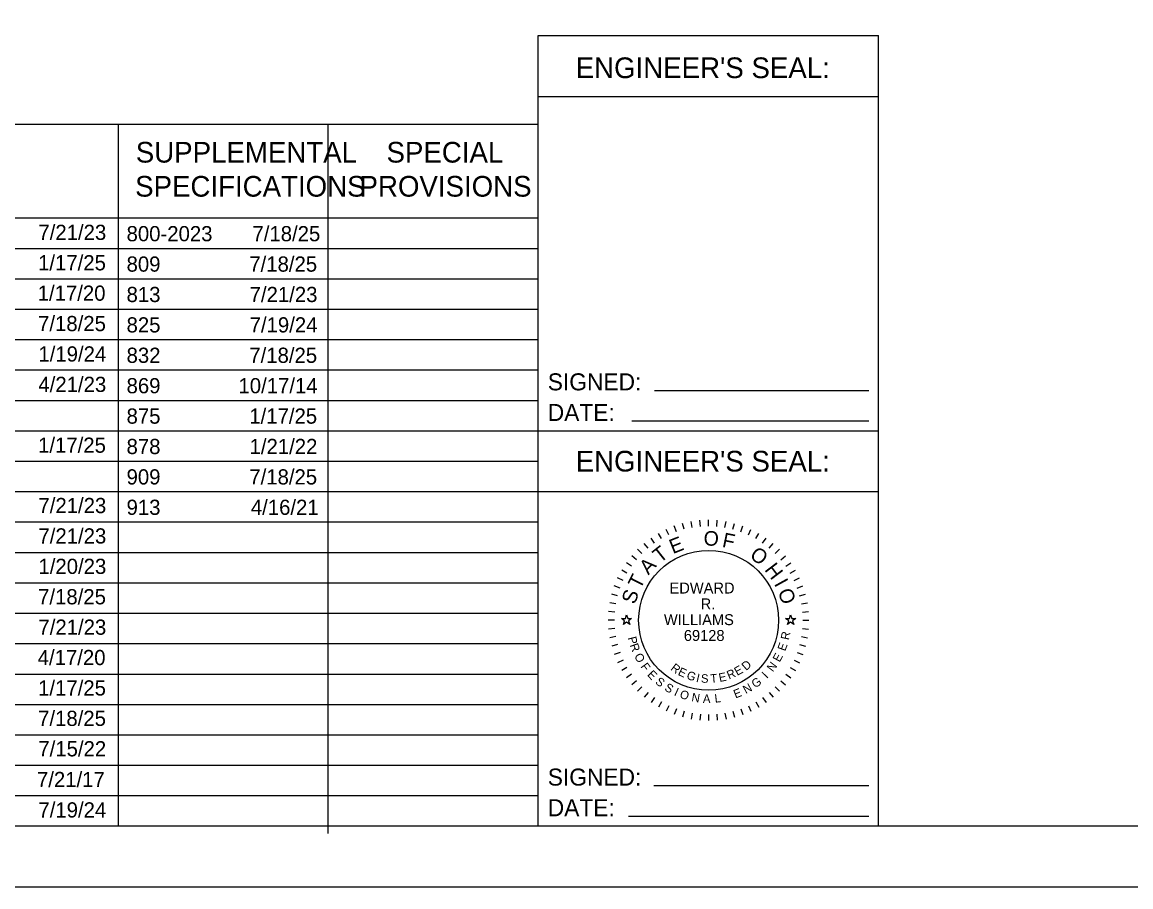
# Model space of a CAD drawing. Extents: x -7.5 to 26.5, y 3.5 to 25.5.
# Drawn here: x 12.51 to 21.63, y 3.5 to 10.61 of the extents above; entities that cross this region are included whole.
import ezdxf

# ---------------------------------------------------------------- set-up
doc = ezdxf.new("R2010")
doc.units = 0
for name, color, linetype in [('SH_Border', 7, 'Continuous'), ('SH_Cut_Line', 7, 'Continuous'), ('SH_Data', 7, 'Continuous'), ('SH_Text', 7, 'Continuous')]:
    doc.layers.add(name, color=color, linetype=linetype)

msp = doc.modelspace()

# ---------------------------------------------------------------- linework, layer by layer
at = {"layer": 'SH_Border'}
msp.add_lwpolyline([(-5.9569, 25), (26.0431, 25), (26.0431, 4), (-5.9569, 4)], close=True, dxfattribs=at)
at = {"layer": 'SH_Cut_Line'}
msp.add_lwpolyline([(-7.4569, 3.5), (26.5431, 3.5), (26.5431, 25.5), (-7.4569, 25.5)], close=True, dxfattribs=at)
at = {"layer": 'SH_Data'}
for p, q in [((16.7556, 7.25), (16.7556, 10.5)), ((16.7556, 10.5), (19.5556, 10.5)), ((19.5556, 4), (19.5556, 10.5)), ((16.7556, 10), (19.5556, 10)), ((1.3056, 9.7708), (16.7556, 9.7708)), ((13.3056, 4), (13.3056, 9.7708)), ((15.0306, 3.9373), (15.0306, 9.7708)), ((1.3056, 9), (16.7556, 9)), ((16.7556, 4), (16.7556, 8.7918)), ((1.3056, 8.75), (16.7556, 8.75)), ((1.3056, 8.5), (16.7556, 8.5)), ((1.3056, 8.25), (16.7556, 8.25)), ((1.3056, 8), (16.7556, 8)), ((1.3056, 7.75), (16.7556, 7.75)), ((1.3056, 7.5), (16.7556, 7.5)), ((1.3056, 7.25), (16.7556, 7.25)), ((16.7556, 4), (16.7556, 7.25)), ((16.7556, 7.25), (19.5556, 7.25)), ((1.3056, 7), (16.7556, 7)), ((1.3056, 6.75), (16.7556, 6.75)), ((16.7556, 6.75), (19.5556, 6.75)), ((1.3056, 6.5), (16.7556, 6.5)), ((1.3056, 6.25), (16.7556, 6.25)), ((1.3056, 6), (16.7556, 6)), ((1.3056, 5.75), (16.7556, 5.75)), ((1.3056, 5.5), (16.7556, 5.5)), ((1.3056, 5.25), (16.7556, 5.25)), ((1.3056, 5), (16.7556, 5)), ((1.3056, 4.75), (16.7556, 4.75)), ((1.3056, 4.5), (16.7556, 4.5)), ((1.3056, 4.25), (16.7556, 4.25))]:
    msp.add_line(p, q, dxfattribs=at)
at = {"layer": 'SH_Text'}
for p, q in [((17.7138, 7.5824), (19.4769, 7.5824)), ((17.5276, 7.3305), (19.4769, 7.3305)), ((17.9576, 6.4405), (17.9447, 6.4888)), ((17.9576, 6.4405), (17.9447, 6.4888)), ((18.0236, 6.4551), (18.015, 6.5043)), ((18.0236, 6.4551), (18.015, 6.5043)), ((18.0907, 6.4639), (18.0863, 6.5137)), ((18.0907, 6.4639), (18.0863, 6.5137)), ((18.1582, 6.4669), (18.1582, 6.5169)), ((18.1582, 6.4669), (18.1582, 6.5169)), ((18.2258, 6.4639), (18.2301, 6.5137)), ((18.2258, 6.4639), (18.2301, 6.5137)), ((18.2928, 6.4551), (18.3015, 6.5043)), ((18.2928, 6.4551), (18.3015, 6.5043)), ((18.3588, 6.4405), (18.3717, 6.4888)), ((18.3588, 6.4405), (18.3717, 6.4888)), ((17.7707, 6.3631), (17.7457, 6.4064)), ((17.7707, 6.3631), (17.7457, 6.4064)), ((17.8307, 6.3943), (17.8096, 6.4396)), ((17.8307, 6.3943), (17.8096, 6.4396)), ((17.8932, 6.4201), (17.8761, 6.4671)), ((17.8932, 6.4201), (17.8761, 6.4671)), ((18.4233, 6.4201), (18.4404, 6.4671)), ((18.4233, 6.4201), (18.4404, 6.4671)), ((18.4857, 6.3943), (18.5069, 6.4396)), ((18.4857, 6.3943), (18.5069, 6.4396)), ((18.5457, 6.3631), (18.5707, 6.4064)), ((18.5457, 6.3631), (18.5707, 6.4064)), ((17.6601, 6.2856), (17.6279, 6.3239)), ((17.6601, 6.2856), (17.6279, 6.3239)), ((17.7137, 6.3267), (17.685, 6.3677)), ((17.7137, 6.3267), (17.685, 6.3677)), ((18.6027, 6.3267), (18.6314, 6.3677)), ((18.6027, 6.3267), (18.6314, 6.3677)), ((18.6564, 6.2856), (18.6885, 6.3239)), ((18.6564, 6.2856), (18.6885, 6.3239)), ((17.5645, 6.19), (17.5262, 6.2222)), ((17.5645, 6.19), (17.5262, 6.2222)), ((17.6102, 6.2399), (17.5749, 6.2752)), ((17.6102, 6.2399), (17.5749, 6.2752)), ((18.7062, 6.2399), (18.7416, 6.2752)), ((18.7062, 6.2399), (18.7416, 6.2752)), ((18.7519, 6.19), (18.7902, 6.2222)), ((18.7519, 6.19), (18.7902, 6.2222)), ((17.5234, 6.1364), (17.4824, 6.1651)), ((17.5234, 6.1364), (17.4824, 6.1651)), ((18.7931, 6.1364), (18.834, 6.1651)), ((18.7931, 6.1364), (18.834, 6.1651)), ((17.4558, 6.0194), (17.4105, 6.0405)), ((17.4558, 6.0194), (17.4105, 6.0405)), ((17.4871, 6.0794), (17.4438, 6.1044)), ((17.4871, 6.0794), (17.4438, 6.1044)), ((18.8294, 6.0794), (18.8727, 6.1044)), ((18.8294, 6.0794), (18.8727, 6.1044)), ((18.8606, 6.0194), (18.9059, 6.0405)), ((18.8606, 6.0194), (18.9059, 6.0405)), ((17.43, 5.9569), (17.383, 5.974)), ((17.43, 5.9569), (17.383, 5.974)), ((18.8865, 5.9569), (18.9335, 5.974)), ((18.8865, 5.9569), (18.9335, 5.974)), ((17.395, 5.8265), (17.3458, 5.8351)), ((17.395, 5.8265), (17.3458, 5.8351)), ((17.4096, 5.8925), (17.3613, 5.9054)), ((17.4096, 5.8925), (17.3613, 5.9054)), ((18.9068, 5.8925), (18.9551, 5.9054)), ((18.9068, 5.8925), (18.9551, 5.9054)), ((18.9214, 5.8265), (18.9707, 5.8351)), ((18.9214, 5.8265), (18.9707, 5.8351)), ((17.3862, 5.7594), (17.3364, 5.7638)), ((17.3862, 5.7594), (17.3364, 5.7638)), ((18.9303, 5.7594), (18.9801, 5.7638)), ((18.9303, 5.7594), (18.9801, 5.7638)), ((17.3832, 5.6919), (17.3332, 5.6919)), ((17.3832, 5.6919), (17.3332, 5.6919)), ((18.9332, 5.6919), (18.9832, 5.6919)), ((18.9332, 5.6919), (18.9832, 5.6919)), ((17.3862, 5.6243), (17.3364, 5.62)), ((17.3862, 5.6243), (17.3364, 5.62)), ((18.9303, 5.6243), (18.9801, 5.62)), ((18.9303, 5.6243), (18.9801, 5.62)), ((17.395, 5.5573), (17.3458, 5.5486)), ((17.395, 5.5573), (17.3458, 5.5486)), ((17.4096, 5.4913), (17.3613, 5.4784)), ((17.4096, 5.4913), (17.3613, 5.4784)), ((18.9068, 5.4913), (18.9551, 5.4784)), ((18.9068, 5.4913), (18.9551, 5.4784)), ((18.9214, 5.5573), (18.9707, 5.5486)), ((18.9214, 5.5573), (18.9707, 5.5486)), ((17.43, 5.4268), (17.383, 5.4097)), ((17.43, 5.4268), (17.383, 5.4097)), ((18.8865, 5.4268), (18.9335, 5.4097)), ((18.8865, 5.4268), (18.9335, 5.4097)), ((17.4558, 5.3644), (17.4105, 5.3432)), ((17.4558, 5.3644), (17.4105, 5.3432)), ((17.4871, 5.3044), (17.4438, 5.2794)), ((17.4871, 5.3044), (17.4438, 5.2794)), ((18.8294, 5.3044), (18.8727, 5.2794)), ((18.8294, 5.3044), (18.8727, 5.2794)), ((18.8606, 5.3644), (18.9059, 5.3432)), ((18.8606, 5.3644), (18.9059, 5.3432)), ((17.5234, 5.2474), (17.4824, 5.2187)), ((17.5234, 5.2474), (17.4824, 5.2187)), ((18.7931, 5.2474), (18.834, 5.2187)), ((18.7931, 5.2474), (18.834, 5.2187)), ((17.5645, 5.1937), (17.5262, 5.1616)), ((17.5645, 5.1937), (17.5262, 5.1616)), ((17.6102, 5.1439), (17.5749, 5.1085)), ((17.6102, 5.1439), (17.5749, 5.1085)), ((18.7062, 5.1439), (18.7416, 5.1085)), ((18.7062, 5.1439), (18.7416, 5.1085)), ((18.7519, 5.1937), (18.7902, 5.1616)), ((18.7519, 5.1937), (18.7902, 5.1616)), ((17.6601, 5.0982), (17.6279, 5.0599)), ((17.6601, 5.0982), (17.6279, 5.0599)), ((17.7137, 5.057), (17.685, 5.0161)), ((17.7137, 5.057), (17.685, 5.0161)), ((17.7707, 5.0207), (17.7457, 4.9774)), ((17.7707, 5.0207), (17.7457, 4.9774)), ((18.5457, 5.0207), (18.5707, 4.9774)), ((18.5457, 5.0207), (18.5707, 4.9774)), ((18.6027, 5.057), (18.6314, 5.0161)), ((18.6027, 5.057), (18.6314, 5.0161)), ((18.6564, 5.0982), (18.6885, 5.0599)), ((18.6564, 5.0982), (18.6885, 5.0599)), ((17.8307, 4.9895), (17.8096, 4.9442)), ((17.8307, 4.9895), (17.8096, 4.9442)), ((17.8932, 4.9636), (17.8761, 4.9166)), ((17.8932, 4.9636), (17.8761, 4.9166)), ((17.9576, 4.9433), (17.9447, 4.895)), ((17.9576, 4.9433), (17.9447, 4.895)), ((18.0236, 4.9287), (18.015, 4.8794)), ((18.0236, 4.9287), (18.015, 4.8794)), ((18.2928, 4.9287), (18.3015, 4.8794)), ((18.2928, 4.9287), (18.3015, 4.8794)), ((18.3588, 4.9433), (18.3717, 4.895)), ((18.3588, 4.9433), (18.3717, 4.895)), ((18.4233, 4.9636), (18.4404, 4.9166)), ((18.4233, 4.9636), (18.4404, 4.9166)), ((18.4857, 4.9895), (18.5069, 4.9442)), ((18.4857, 4.9895), (18.5069, 4.9442)), ((18.0907, 4.9198), (18.0863, 4.87)), ((18.0907, 4.9198), (18.0863, 4.87)), ((18.1582, 4.9169), (18.1582, 4.8669)), ((18.1582, 4.9169), (18.1582, 4.8669)), ((18.2258, 4.9198), (18.2301, 4.87)), ((18.2258, 4.9198), (18.2301, 4.87)), ((17.7067, 4.3324), (19.4769, 4.3324)), ((17.499, 4.0805), (19.4769, 4.0805))]:
    msp.add_line(p, q, dxfattribs=at)
for points in [[(17.4837, 5.7356), (17.4935, 5.7054), (17.5253, 5.7054), (17.4996, 5.6867), (17.5094, 5.6565), (17.4837, 5.6752), (17.458, 5.6565), (17.4679, 5.6867), (17.4422, 5.7054), (17.4739, 5.7054)], [(17.4837, 5.7356), (17.4935, 5.7054), (17.5253, 5.7054), (17.4996, 5.6867), (17.5094, 5.6565), (17.4837, 5.6752), (17.458, 5.6565), (17.4679, 5.6867), (17.4422, 5.7054), (17.4739, 5.7054)], [(18.8327, 5.7356), (18.8425, 5.7054), (18.8743, 5.7054), (18.8486, 5.6867), (18.8584, 5.6565), (18.8327, 5.6752), (18.807, 5.6565), (18.8168, 5.6867), (18.7912, 5.7054), (18.8229, 5.7054)], [(18.8327, 5.7356), (18.8425, 5.7054), (18.8743, 5.7054), (18.8486, 5.6867), (18.8584, 5.6565), (18.8327, 5.6752), (18.807, 5.6565), (18.8168, 5.6867), (18.7912, 5.7054), (18.8229, 5.7054)]]:
    msp.add_lwpolyline(points, close=True, dxfattribs=at)
msp.add_circle((18.1582, 5.6919), 0.575, dxfattribs=at)
msp.add_circle((18.1582, 5.6919), 0.575, dxfattribs=at)

# ---------------------------------------------------------------- texts
for s, height, p in [("ENGINEER'S SEAL:", 0.17, (17.0651, 10.15)), ('SUPPLEMENTAL', 0.17, (13.4481, 9.4554)), ('SPECIAL', 0.17, (15.5098, 9.4554)), ('SPECIFICATIONS', 0.17, (13.4426, 9.1754)), ('PROVISIONS', 0.17, (15.2879, 9.1754)), ('7/21/23', 0.125, (12.6473, 8.8193)), ('800-2023', 0.125, (13.3722, 8.8084)), ('7/18/25', 0.125, (14.4074, 8.8084)), ('1/17/25', 0.125, (12.6446, 8.5693)), ('809', 0.125, (13.3722, 8.5584)), ('7/18/25', 0.125, (14.3815, 8.5584)), ('1/17/20', 0.125, (12.6412, 8.3193)), ('813', 0.125, (13.3722, 8.3084)), ('7/21/23', 0.125, (14.3842, 8.3084)), ('7/18/25', 0.125, (12.6446, 8.0693)), ('825', 0.125, (13.3722, 8.0584)), ('7/19/24', 0.125, (14.3842, 8.0584)), ('1/19/24', 0.125, (12.6473, 7.8193)), ('832', 0.125, (13.3722, 7.8084)), ('7/18/25', 0.125, (14.3815, 7.8084)), ('4/21/23', 0.125, (12.6473, 7.5693)), ('869', 0.125, (13.3722, 7.5584)), ('10/17/14', 0.125, (14.2924, 7.5584)), ('SIGNED:', 0.14, (16.8356, 7.5824)), ('875', 0.125, (13.3722, 7.3084)), ('1/17/25', 0.125, (14.3815, 7.3084)), ('DATE:', 0.14, (16.8356, 7.3305)), ('1/17/25', 0.125, (12.6446, 7.0693)), ('878', 0.125, (13.3722, 7.0584)), ('1/21/22', 0.125, (14.3836, 7.0584)), ("ENGINEER'S SEAL:", 0.17, (17.0651, 6.915)), ('909', 0.125, (13.3722, 6.8084)), ('7/18/25', 0.125, (14.3815, 6.8084)), ('7/21/23', 0.125, (12.6476, 6.5729)), ('913', 0.125, (13.3722, 6.5584)), ('4/16/21', 0.125, (14.3942, 6.5584)), ('7/21/23', 0.125, (12.6476, 6.3229)), ('1/20/23', 0.125, (12.6476, 6.0729)), ('7/18/25', 0.125, (12.6449, 5.8229)), ('EDWARD', 0.09, (17.8369, 5.9119)), ('R.', 0.09, (18.0928, 5.7819)), ('7/21/23', 0.125, (12.6476, 5.5729)), ('WILLIAMS', 0.09, (17.7909, 5.6519)), ('69128', 0.09, (17.9546, 5.5219)), ('4/17/20', 0.125, (12.6415, 5.3229)), ('1/17/25', 0.125, (12.6449, 5.0729)), ('7/18/25', 0.125, (12.6449, 4.8229)), ('7/15/22', 0.125, (12.6467, 4.5729)), ('SIGNED:', 0.14, (16.8356, 4.3324)), ('7/21/17', 0.125, (12.6355, 4.32)), ('7/19/24', 0.125, (12.6473, 4.07)), ('DATE:', 0.14, (16.8356, 4.0805))]:
    msp.add_text(s, height=height, dxfattribs=at).set_placement(p)
for s, height, rotation, p in [('E', 0.12, 21.76545, (17.8645, 6.2352)), ('E', 0.12, 21.76545, (17.8645, 6.2352)), ('O', 0.12, 356.92868, (18.1148, 6.3086)), ('O', 0.12, 356.92868, (18.1148, 6.3086)), ('F', 0.12, 348.64976, (18.2647, 6.2962)), ('F', 0.12, 348.64976, (18.2647, 6.2962)), ('T', 0.12, 38.32329, (17.7589, 6.1582)), ('T', 0.12, 38.32329, (17.7589, 6.1582)), ('O', 0.12, 323.81299, (18.4888, 6.2102)), ('O', 0.12, 323.81299, (18.4888, 6.2102)), ('A', 0.12, 46.60221, (17.6629, 6.0609)), ('A', 0.12, 46.60221, (17.6629, 6.0609)), ('H', 0.12, 307.25515, (18.6135, 6.1067)), ('H', 0.12, 307.25515, (18.6135, 6.1067)), ('T', 0.12, 63.16006, (17.5968, 5.941)), ('T', 0.12, 63.16006, (17.5968, 5.941)), ('I', 0.12, 298.97623, (18.6933, 5.992)), ('I', 0.12, 298.97623, (18.6933, 5.992)), ('S', 0.12, 71.43898, (17.5533, 5.8178)), ('S', 0.12, 71.43898, (17.5533, 5.8178)), ('O', 0.12, 290.69731, (18.7249, 5.928)), ('O', 0.12, 290.69731, (18.7249, 5.928)), ('R', 0.07, 78.25391, (18.8182, 5.5257)), ('R', 0.07, 78.25391, (18.8182, 5.5257)), ('P', 0.07, 284.38864, (17.493, 5.5485)), ('P', 0.07, 284.38864, (17.493, 5.5485)), ('R', 0.07, 289.85343, (17.509, 5.4876)), ('R', 0.07, 289.85343, (17.509, 5.4876)), ('E', 0.07, 69.93316, (18.7877, 5.4332)), ('E', 0.07, 69.93316, (18.7877, 5.4332)), ('O', 0.07, 298.2291, (17.544, 5.3984)), ('O', 0.07, 298.2291, (17.544, 5.3984)), ('E', 0.07, 61.36526, (18.7421, 5.3423)), ('E', 0.07, 61.36526, (18.7421, 5.3423)), ('F', 0.07, 306.22032, (17.5948, 5.3103)), ('F', 0.07, 306.22032, (17.5948, 5.3103)), ('R', 0.07, 322.75006, (17.8404, 5.2875)), ('R', 0.07, 322.75006, (17.8404, 5.2875)), ('E', 0.07, 334.84097, (17.9006, 5.2448)), ('E', 0.07, 334.84097, (17.9006, 5.2448)), ('R', 0.07, 23.20461, (18.3256, 5.2044)), ('R', 0.07, 23.20461, (18.3256, 5.2044)), ('E', 0.07, 29.25007, (18.3934, 5.2338)), ('E', 0.07, 29.25007, (18.3934, 5.2338)), ('D', 0.07, 41.34098, (18.4667, 5.274)), ('D', 0.07, 41.34098, (18.4667, 5.274)), ('N', 0.07, 53.34658, (18.6865, 5.2627)), ('N', 0.07, 53.34658, (18.6865, 5.2627)), ('E', 0.07, 313.82708, (17.6489, 5.2405)), ('E', 0.07, 313.82708, (17.6489, 5.2405)), ('S', 0.07, 321.65353, (17.7145, 5.1758)), ('S', 0.07, 321.65353, (17.7145, 5.1758)), ('G', 0.07, 340.88642, (17.9713, 5.2125)), ('G', 0.07, 340.88642, (17.9713, 5.2125)), ('I', 0.07, 346.93188, (18.0511, 5.1861)), ('I', 0.07, 346.93188, (18.0511, 5.1861)), ('S', 0.07, 359.02279, (18.0948, 5.1786)), ('S', 0.07, 359.02279, (18.0948, 5.1786)), ('T', 0.07, 5.06825, (18.1755, 5.1771)), ('T', 0.07, 5.06825, (18.1755, 5.1771)), ('E', 0.07, 11.1137, (18.2488, 5.184)), ('E', 0.07, 11.1137, (18.2488, 5.184)), ('G', 0.07, 37.17191, (18.5432, 5.1304)), ('G', 0.07, 37.17191, (18.5432, 5.1304)), ('I', 0.07, 45.35536, (18.6366, 5.2086)), ('I', 0.07, 45.35536, (18.6366, 5.2086)), ('S', 0.07, 329.56237, (17.7897, 5.1197)), ('S', 0.07, 329.56237, (17.7897, 5.1197)), ('I', 0.07, 335.46653, (17.8688, 5.0765)), ('I', 0.07, 335.46653, (17.8688, 5.0765)), ('O', 0.07, 341.78261, (17.9153, 5.056)), ('O', 0.07, 341.78261, (17.9153, 5.056)), ('E', 0.07, 21.2444, (18.3794, 5.0483)), ('E', 0.07, 21.2444, (18.3794, 5.0483)), ('N', 0.07, 29.18069, (18.4645, 5.0841)), ('N', 0.07, 29.18069, (18.4645, 5.0841)), ('N', 0.07, 350.21321, (18.0141, 5.0267)), ('N', 0.07, 350.21321, (18.0141, 5.0267)), ('A', 0.07, 358.61635, (18.1107, 5.0128)), ('A', 0.07, 358.61635, (18.1107, 5.0128)), ('L', 0.07, 6.49772, (18.2111, 5.0135)), ('L', 0.07, 6.49772, (18.2111, 5.0135))]:
    msp.add_text(s, height=height, rotation=rotation, dxfattribs=at).set_placement(p)

doc.saveas('drawing.dxf')
